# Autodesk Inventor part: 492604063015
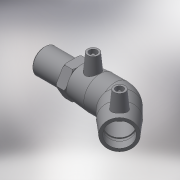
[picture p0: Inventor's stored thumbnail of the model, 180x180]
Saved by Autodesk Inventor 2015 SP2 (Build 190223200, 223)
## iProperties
Created: 2017-06
Part Number: 492604063015
Material: Generic
Description: PLASSON 45° ELBOW TRANSITION MALE 63-1.1/2"
Document SubType Name: Modeling
Designer: KIM
Mass: 481.042 g
Surface Area: 856.685 cm^2
Volume: 481.042 cm^3
Density: 1 g/cm^3
Appearance: Default
Author: KIM
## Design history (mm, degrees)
derived "492604.ipt"
feature "Solid1::492604.ipt"
tag "TaggingFeature1"
body "Solid1"
other parameters: "d2" = 82, "d4" = 37, "d5" = 73.8, "d8" = 168 deg, "d10" = 22.8, "d11" = 7.6, "d29" = 59, "d30" = 15, "d31" = 51.8, "d34" = 5 deg, "d41" = 4, "d42" = 14, "d43" = 0, "d49" = 63, "d50" = 40.95, "d51" = 22.8, "d52" = 58.71, "d54" = 135 deg, "d86" = 36.9, "d87" = 135 deg, "d88" = 148, "d90" = 57, "d91" = 0, "d92" = 57, "d93" = 0, "d101" = 3, "d102" = 0, "d107" = 0.1, "d108" = 48, "d109" = 47.803, "d110" = 36, "d111" = 9, "d112" = 82, "d113" = 33.4621, "d114" = 32.4, "d116" = 2.46, "d122" = 0, "d123" = 2.39015, "d_" = 63, "L_" = 184, "L_1" = 57, "D_" = 48, "A_" = 59, "d_2" = 12, "L_2" = 36, "R_" = 47.803, "D_1" = 82
